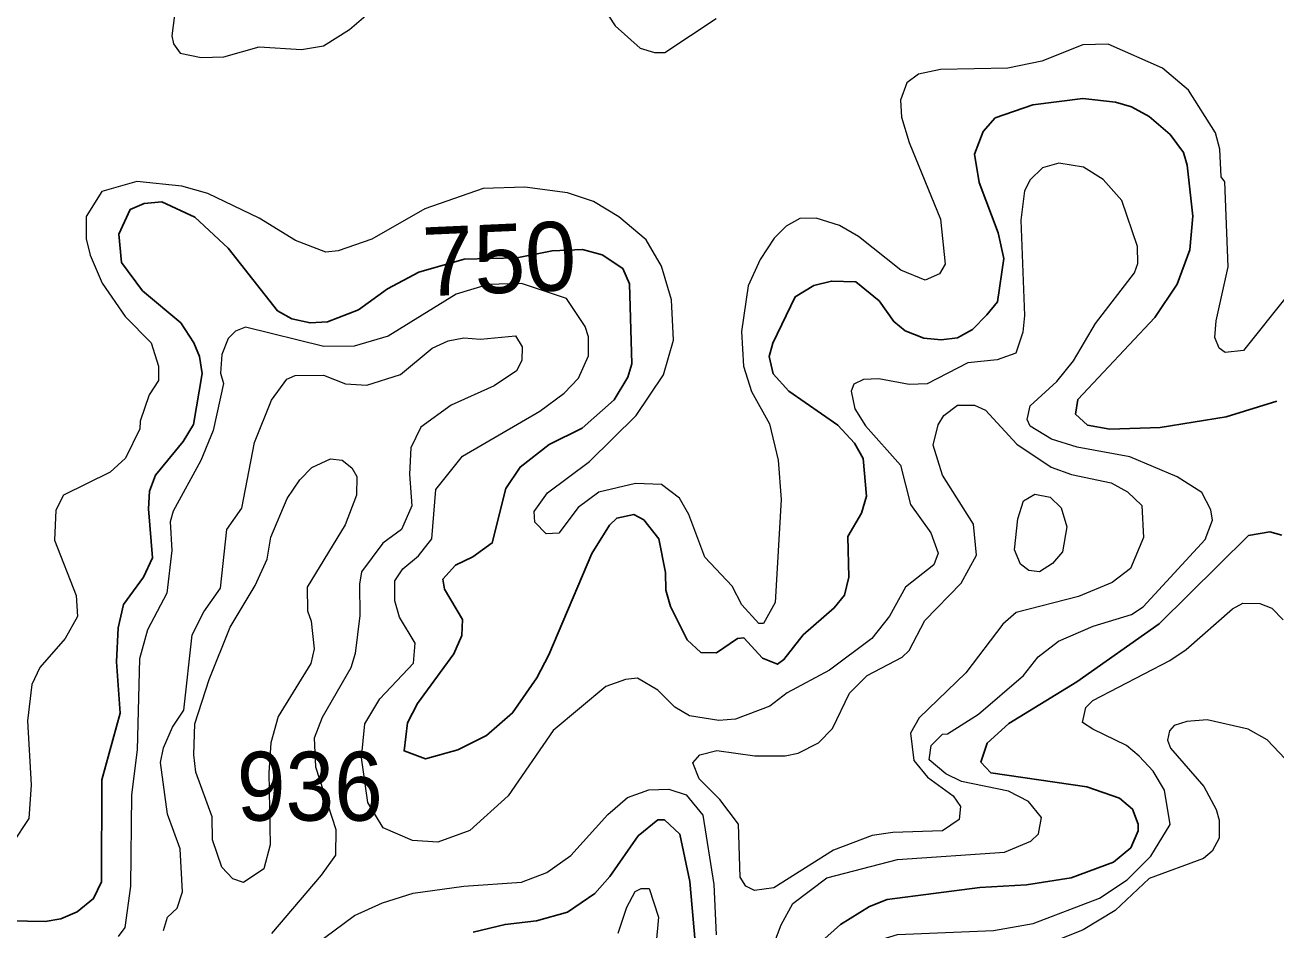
# Model space of a CAD drawing. Extents: x 763.2 to 816.8, y 7896.5 to 7952.7.
# Drawn here: x 774.565 to 777.47, y 7924.125 to 7926.226 of the extents above; entities that cross this region are included whole.
import ezdxf
from ezdxf.enums import TextEntityAlignment as Align

# ---------------------------------------------------------------- set-up
doc = ezdxf.new("R2010")
doc.units = 0
doc.header["$LTSCALE"] = 0.064
doc.layers.add('1', color=7, linetype='Continuous', lineweight=25)
doc.layers.add('2', color=7, linetype='Continuous', lineweight=13)
doc.layers.add('21', color=7, linetype='Continuous')
doc.layers.add('61', color=7, linetype='Continuous')

msp = doc.modelspace()

# ---------------------------------------------------------------- linework, layer by layer
at = {"layer": '1'}
for points in [[(776.1029, 7924.7983), (776.1344, 7924.7692), (776.1706, 7924.7687), (776.2194, 7924.8015), (776.2341, 7924.8031), (776.2781, 7924.7558), (776.3122, 7924.7417), (776.3275, 7924.7526), (776.3725, 7924.8102), (776.4445, 7924.8728), (776.4685, 7924.902), (776.4783, 7924.9438), (776.4756, 7925.0388), (776.508, 7925.0925), (776.5196, 7925.1319), (776.5113, 7925.22), (776.4913, 7925.2556), (776.4527, 7925.2973), (776.339, 7925.3761), (776.3024, 7925.4164), (776.2933, 7925.4565), (776.3016, 7925.4874), (776.3539, 7925.5951), (776.3966, 7925.6215), (776.4377, 7925.6315), (776.4943, 7925.6295), (776.5485, 7925.5859), (776.5827, 7925.5376), (776.6092, 7925.5162), (776.6521, 7925.4988), (776.693, 7925.4953), (776.7309, 7925.5), (776.7658, 7925.5195), (776.799, 7925.5529), (776.8236, 7925.5831), (776.8384, 7925.6843), (776.825, 7925.744), (776.7812, 7925.8609), (776.7702, 7925.9262), (776.7906, 7925.9792), (776.8184, 7926.0104), (776.9058, 7926.0413), (777.0217, 7926.0553), (777.0973, 7926.0471), (777.1351, 7926.0359), (777.176, 7926.0139), (777.2243, 7925.9721), (777.2556, 7925.9306), (777.2641, 7925.901), (777.2772, 7925.782), (777.2706, 7925.7039), (777.2407, 7925.6243), (777.189, 7925.5467), (777.0103, 7925.3565), (777.0049, 7925.3226), (777.0324, 7925.2972), (777.0842, 7925.2881), (777.2015, 7925.2917), (777.3547, 7925.3163), (777.4722, 7925.3529)], [(774.5295, 7924.1458), (774.6115, 7924.1447), (774.6478, 7924.1509), (774.6859, 7924.1667), (774.7241, 7924.1977), (774.7427, 7924.2362), (774.7432, 7924.4738), (774.7857, 7924.6283), (774.7777, 7924.7473), (774.781, 7924.8262), (774.7939, 7924.8807), (774.8397, 7924.9439), (774.8612, 7924.9891), (774.8516, 7925.1024), (774.8539, 7925.1434), (774.8682, 7925.1812), (774.9325, 7925.2591), (774.9563, 7925.2989), (774.9763, 7925.4171), (774.97, 7925.4566), (774.9569, 7925.4885), (774.9266, 7925.5347), (774.838, 7925.6091), (774.7891, 7925.675), (774.7829, 7925.7406), (774.8089, 7925.7982), (774.8418, 7925.8121), (774.8825, 7925.8154), (774.9593, 7925.7797), (775.0368, 7925.7077), (775.1509, 7925.5627), (775.1843, 7925.5443), (775.2271, 7925.5346), (775.2674, 7925.5367), (775.3397, 7925.565), (775.407, 7925.6134), (775.4792, 7925.6523), (775.5846, 7925.6829), (775.7072, 7925.6856), (775.7889, 7925.702), (775.8597, 7925.7047), (775.9053, 7925.6929), (775.9533, 7925.661), (775.969, 7925.6249), (775.974, 7925.4392), (775.965, 7925.4084), (775.9333, 7925.3561), (775.859, 7925.2898), (775.7819, 7925.2518), (775.7151, 7925.1997), (775.6818, 7925.1497), (775.6499, 7925.0236), (775.6049, 7924.991), (775.5649, 7924.9722), (775.5355, 7924.9396), (775.5389, 7924.916), (775.5809, 7924.8459), (775.5796, 7924.8083), (775.5611, 7924.7664), (775.4761, 7924.6503), (775.4532, 7924.606), (775.4453, 7924.5406), (775.495, 7924.5225), (775.5698, 7924.543), (775.6364, 7924.5762), (775.6974, 7924.6288), (775.7534, 7924.7105), (775.7817, 7924.7637), (775.8813, 7924.9987), (775.9221, 7925.0646), (775.9394, 7925.0814), (775.9792, 7925.0899), (776.002, 7925.0774)], [(776.002, 7925.0774), (776.0371, 7925.0332), (776.0527, 7924.9552), (776.0532, 7924.9142), (776.0642, 7924.8763), (776.1029, 7924.7983)], [(777.4837, 7925.0417), (777.4564, 7925.0495), (777.4066, 7925.041), (777.1994, 7924.8356), (777.0078, 7924.7013), (776.8501, 7924.6043), (776.7992, 7924.5582), (776.7852, 7924.5143), (776.8082, 7924.4893), (777.0311, 7924.457), (777.107, 7924.4312), (777.1374, 7924.4053), (777.1504, 7924.3701), (777.1501, 7924.3547), (777.1333, 7924.3158), (777.0931, 7924.2823), (776.9946, 7924.2462), (776.8911, 7924.2298), (776.7827, 7924.2232), (776.5671, 7924.1957), (776.5263, 7924.1795), (776.4588, 7924.1376), (776.408, 7924.0916)], [(776.1235, 7924.071), (776.1089, 7924.2371), (776.0856, 7924.3473), (776.05, 7924.3803), (776.0349, 7924.3806), (775.9887, 7924.343), (775.9231, 7924.2488), (775.8882, 7924.2096), (775.8252, 7924.1659), (775.753, 7924.146), (775.6799, 7924.1376), (775.606, 7924.1193)]]:
    msp.add_lwpolyline(points, dxfattribs=at)
at = {"layer": '2'}
for points in [[(775.8797, 7926.31), (775.9355, 7926.2244), (775.9938, 7926.1723), (776.027, 7926.1626), (776.0512, 7926.1626), (776.1698, 7926.2417)], [(774.9124, 7926.2489), (774.9058, 7926.2008), (774.9099, 7926.1825), (774.9252, 7926.1606), (774.9739, 7926.1509), (775.0265, 7926.1527), (775.1087, 7926.1754), (775.2073, 7926.1691), (775.258, 7926.1781), (775.3186, 7926.216), (775.378, 7926.2667)], [(777.0803, 7926.1819), (777.0217, 7926.1805), (776.9266, 7926.1422), (776.8476, 7926.1262), (776.6908, 7926.1226), (776.6397, 7926.1119)], [(777.4966, 7925.5974), (777.3952, 7925.4705), (777.3527, 7925.466), (777.3381, 7925.476), (777.3284, 7925.5007), (777.3316, 7925.5394), (777.3595, 7925.6646), (777.3512, 7925.8621), (777.343, 7925.8739), (777.3396, 7925.9379), (777.3301, 7925.9759), (777.2674, 7926.0752), (777.2066, 7926.126), (777.0803, 7926.1819)], [(776.6397, 7926.1119), (776.6127, 7926.0918), (776.5986, 7926.0518), (776.6005, 7926.0122), (776.6183, 7925.9536), (776.6908, 7925.7755), (776.7018, 7925.6711), (776.6891, 7925.6486), (776.6555, 7925.6334), (776.5991, 7925.6566), (776.501, 7925.7354), (776.4567, 7925.7606), (776.4024, 7925.7777), (776.3642, 7925.7773), (776.3326, 7925.7593), (776.3047, 7925.7313), (776.2725, 7925.6821), (776.2448, 7925.6203), (776.2288, 7925.5143), (776.2338, 7925.4343), (776.2519, 7925.3752), (776.2941, 7925.3002), (776.3144, 7925.216), (776.3209, 7925.1245), (776.3074, 7924.8856), (776.2799, 7924.8366), (776.2695, 7924.8361), (776.2295, 7924.8801), (776.2076, 7924.9228), (776.1435, 7924.9906), (776.1068, 7925.0897), (776.085, 7925.1274), (776.0429, 7925.1589), (775.983, 7925.1615), (775.8978, 7925.1418), (775.8499, 7925.1061), (775.8049, 7925.0463), (775.7755, 7925.045), (775.749, 7925.0719), (775.7475, 7925.0967), (775.7785, 7925.1401), (775.8756, 7925.2123), (775.9844, 7925.3198), (776.0476, 7925.414), (776.071, 7925.4941), (776.0661, 7925.588), (776.0435, 7925.6663), (776.0079, 7925.7273), (775.9444, 7925.781), (775.8851, 7925.8165), (775.8245, 7925.8368), (775.7259, 7925.85), (775.6288, 7925.8467), (775.4938, 7925.7997), (775.3701, 7925.7287), (775.292, 7925.7022), (775.2636, 7925.6989), (775.1928, 7925.7255), (775.109, 7925.778), (774.9896, 7925.8351), (774.9291, 7925.852), (774.8247, 7925.8632), (774.743, 7925.8396), (774.7071, 7925.7819), (774.707, 7925.7301), (774.7164, 7925.692), (774.7442, 7925.6271), (774.7977, 7925.5496), (774.8576, 7925.4885), (774.8745, 7925.4343), (774.8746, 7925.4011), (774.8533, 7925.3678), (774.8322, 7925.3067), (774.8313, 7925.2883), (774.7984, 7925.2205), (774.7623, 7925.1875), (774.6539, 7925.1343), (774.6366, 7925.0997), (774.6333, 7925.0302), (774.684, 7924.9012), (774.687, 7924.8525), (774.6584, 7924.802), (774.5993, 7924.7344), (774.5805, 7924.6947), (774.5706, 7924.6108), (774.5788, 7924.4621), (774.5739, 7924.3833), (774.5356, 7924.3265)], [(777.1126, 7925.8185), (777.069, 7925.8676), (777.0236, 7925.8963), (776.9658, 7925.9058), (776.9281, 7925.8945), (776.8995, 7925.8665), (776.8862, 7925.8411), (776.878, 7925.7728), (776.8861, 7925.5519), (776.8827, 7925.5132), (776.8665, 7925.4645), (776.8227, 7925.4491), (776.7543, 7925.4421), (776.6601, 7925.3928), (776.6182, 7925.3914), (776.5476, 7925.4047), (776.5124, 7925.4028), (776.4901, 7925.3923), (776.4837, 7925.3759), (776.492, 7925.3348), (776.5173, 7925.2954), (776.5982, 7925.2038), (776.6217, 7925.1127), (776.6688, 7925.0471), (776.6856, 7925), (776.6758, 7924.973), (776.6102, 7924.9211), (776.5726, 7924.8531), (776.5313, 7924.802), (776.4332, 7924.7281), (776.3353, 7924.6758), (776.2951, 7924.6442), (776.215, 7924.6141), (776.1762, 7924.611), (776.1083, 7924.6222), (776.0745, 7924.6425), (776.0347, 7924.6817), (775.9872, 7924.7093), (775.9593, 7924.7062), (775.9139, 7924.6901), (775.7917, 7924.5878), (775.6873, 7924.4364), (775.5977, 7924.3561), (775.5235, 7924.3286), (775.4652, 7924.3325), (775.397, 7924.3618), (775.3608, 7924.4206), (775.3463, 7924.5245), (775.3544, 7924.6031), (775.3891, 7924.6618), (775.4669, 7924.7444), (775.4707, 7924.7904), (775.4344, 7924.8515), (775.4236, 7924.8893), (775.4237, 7924.9357), (775.4426, 7924.9636), (775.4788, 7924.9933), (775.5096, 7925.033), (775.519, 7925.1476), (775.5808, 7925.2248), (775.7608, 7925.3299), (775.8174, 7925.3714), (775.8502, 7925.4058), (775.8738, 7925.4581), (775.8739, 7925.5018), (775.8655, 7925.5263), (775.8227, 7925.591), (775.718, 7925.6257), (775.6406, 7925.624), (775.5666, 7925.6014), (775.4085, 7925.504), (775.3296, 7925.4807), (775.2586, 7925.4794), (775.0766, 7925.5244), (775.0534, 7925.5151), (775.0366, 7925.4986), (775.0223, 7925.4615), (775.0192, 7925.4176), (775.0257, 7925.3936), (775.0015, 7925.2845), (774.9735, 7925.2147), (774.9087, 7925.0976), (774.9022, 7925.0722), (774.9057, 7925.0063), (774.8946, 7924.9069), (774.8494, 7924.8215), (774.8304, 7924.7546), (774.8252, 7924.5428), (774.8122, 7924.4383), (774.8101, 7924.2266), (774.7963, 7924.1302), (774.7811, 7924.1093)], [(776.2934, 7924.0629), (776.3211, 7924.1365), (776.3481, 7924.1864), (776.4271, 7924.2456), (776.5915, 7924.2884), (776.8401, 7924.3053), (776.9007, 7924.3306), (776.9185, 7924.3478), (776.9254, 7924.3858), (776.8959, 7924.4234), (776.8493, 7924.4473), (776.7396, 7924.4693), (776.7035, 7924.4872), (776.6649, 7924.5202), (776.6694, 7924.5533), (776.6957, 7924.5792), (776.7072, 7924.5804), (776.7793, 7924.6258), (776.8841, 7924.7157), (776.9181, 7924.7593), (776.9656, 7924.7953), (777.0459, 7924.8306), (777.1346, 7924.857), (777.1618, 7924.8753), (777.3058, 7925.0314), (777.3231, 7925.0761), (777.3194, 7925.1006), (777.2982, 7925.1404), (777.241, 7925.1771), (777.1308, 7925.2234), (777.0088, 7925.2458), (776.9493, 7925.2648), (776.8995, 7925.295), (776.8927, 7925.31), (776.8992, 7925.3416), (776.9616, 7925.3982), (777.0001, 7925.4461), (777.051, 7925.5335), (777.142, 7925.6507), (777.1492, 7925.6724), (777.1489, 7925.7118), (777.1126, 7925.8185)], [(774.8866, 7924.1233), (774.8958, 7924.1547), (774.9184, 7924.1753), (774.9309, 7924.2131), (774.9251, 7924.3129), (774.8958, 7924.3935), (774.8796, 7924.5138), (774.8865, 7924.5474), (774.9072, 7924.5955), (774.9337, 7924.6352), (774.9529, 7924.8099), (774.9801, 7924.8635), (775.019, 7924.9184), (775.0338, 7925.055), (775.0684, 7925.1042), (775.0982, 7925.2568), (775.1373, 7925.3548), (775.1727, 7925.4036), (775.1923, 7925.4126), (775.2579, 7925.4131), (775.3092, 7925.393), (775.3585, 7925.3901), (775.4366, 7925.4146), (775.5102, 7925.4761), (775.5474, 7925.4926), (775.5839, 7925.5), (775.6231, 7925.4969), (775.7038, 7925.5047), (775.7193, 7925.4789), (775.719, 7925.4471), (775.7062, 7925.4234), (775.6542, 7925.3886), (775.5545, 7925.3435), (775.4843, 7925.2925), (775.4613, 7925.2446), (775.458, 7925.1829), (775.4629, 7925.1096), (775.4396, 7925.055), (775.3957, 7925.0231), (775.3465, 7924.9564), (775.3414, 7924.9281), (775.3428, 7924.8552), (775.3314, 7924.767), (775.3213, 7924.7336), (775.2553, 7924.6178), (775.2364, 7924.5705), (775.2396, 7924.5035), (775.2867, 7924.3584), (775.2857, 7924.2988), (775.253, 7924.2517), (775.1376, 7924.1162)], [(776.5048, 7924.0877), (776.5911, 7924.1143), (776.8141, 7924.1233), (776.9066, 7924.1395), (777.0602, 7924.1986), (777.1244, 7924.2412), (777.1793, 7924.2959), (777.2245, 7924.3694), (777.2116, 7924.4491), (777.1852, 7924.4936), (777.1524, 7924.5287), (777.123, 7924.5531), (777.0449, 7924.5908), (777.0211, 7924.6068), (777.029, 7924.6414), (777.0453, 7924.6576), (777.2241, 7924.7503), (777.2614, 7924.7757), (777.3694, 7924.8705), (777.3931, 7924.8838), (777.4326, 7924.8826), (777.4607, 7924.8722), (777.4872, 7924.8446)], [(777.5607, 7924.4496), (777.4498, 7924.5665), (777.4055, 7924.5911), (777.3102, 7924.6124), (777.2635, 7924.609), (777.234, 7924.5998), (777.223, 7924.5872), (777.2186, 7924.5658), (777.2252, 7924.5466), (777.3027, 7924.4577), (777.3317, 7924.4049), (777.3383, 7924.38), (777.3382, 7924.338), (777.3219, 7924.3075), (777.3018, 7924.2907), (777.1755, 7924.2443), (777.0969, 7924.1696), (777.0223, 7924.1251), (776.9551, 7924.0983)], [(775.2372, 7924.0894), (775.3303, 7924.1581), (775.3951, 7924.1877), (775.4663, 7924.2099), (775.584, 7924.2262), (775.7176, 7924.2354), (775.777, 7924.2586), (775.8322, 7924.2979), (775.9188, 7924.3928), (775.9639, 7924.4322), (776.014, 7924.4503), (776.0598, 7924.4517), (776.1001, 7924.4385), (776.1395, 7924.391), (776.1649, 7924.23), (776.1705, 7924.1131)], [(775.9428, 7924.117), (775.9624, 7924.1781), (775.9821, 7924.2141), (775.9961, 7924.2214), (776.0145, 7924.2214), (776.0365, 7924.1544), (776.03, 7924.0873)]]:
    msp.add_lwpolyline(points, dxfattribs=at)
for points in [[(776.7745, 7924.9951), (776.7675, 7925.0668), (776.6956, 7925.1813), (776.6742, 7925.2508), (776.6859, 7925.298), (776.699, 7925.3191), (776.7308, 7925.3438), (776.7703, 7925.3438), (776.7958, 7925.3322), (776.8686, 7925.2532), (776.948, 7925.1996), (776.9953, 7925.1827), (777.0874, 7925.1628), (777.1252, 7925.1422), (777.1587, 7925.1103), (777.1623, 7925.0363), (777.1323, 7924.9645), (777.0899, 7924.9314), (777.0118, 7924.8988), (776.8666, 7924.8622), (776.8359, 7924.8348), (776.7502, 7924.7216), (776.6415, 7924.6174), (776.6216, 7924.5815), (776.6296, 7924.5183), (776.661, 7924.4797), (776.7205, 7924.4361), (776.7379, 7924.4115), (776.7347, 7924.3811), (776.6956, 7924.3548), (776.5805, 7924.3512), (776.5321, 7924.3438), (776.4427, 7924.3101), (776.3038, 7924.2229), (776.2593, 7924.2165), (776.2388, 7924.2266), (776.2256, 7924.2476), (776.2221, 7924.3703), (776.1783, 7924.428), (776.1303, 7924.4756), (776.1163, 7924.5132), (776.132, 7924.5318), (776.1715, 7924.5416), (776.2602, 7924.5289), (776.33, 7924.5288), (776.3609, 7924.5357), (776.4075, 7924.5592), (776.4404, 7924.5927), (776.4801, 7924.675), (776.5207, 7924.7155), (776.6023, 7924.758), (776.6181, 7924.7734), (776.6549, 7924.8432), (776.7392, 7924.9304)], [(774.9568, 7924.5312), (774.9592, 7924.6032), (774.9925, 7924.7066), (775.0412, 7924.8276), (775.0997, 7924.9249), (775.1269, 7924.9859), (775.1355, 7925.037), (775.174, 7925.1269), (775.2029, 7925.1702), (775.231, 7925.1988), (775.2742, 7925.2186), (775.3012, 7925.2156), (775.3242, 7925.1979), (775.3355, 7925.1781), (775.3345, 7925.1346), (775.3081, 7925.0655), (775.2199, 7924.9208), (775.221, 7924.8658), (775.2296, 7924.8419), (775.2361, 7924.7774), (775.229, 7924.7439), (775.153, 7924.6205), (775.1358, 7924.5594), (775.1309, 7924.4899), (775.1342, 7924.3226), (775.1199, 7924.2669), (775.0726, 7924.235), (775.0472, 7924.2432), (775.0219, 7924.2705), (775.0001, 7924.3339), (774.9998, 7924.3873), (774.9617, 7924.4916)], [(776.8634, 7925.0077), (776.8705, 7925.0798), (776.8843, 7925.1211), (776.91, 7925.1367), (776.9462, 7925.1295), (776.9716, 7925.1051), (776.9843, 7925.0611), (776.9749, 7925.0027), (776.9516, 7924.9758), (776.9209, 7924.9562), (776.8962, 7924.9596), (776.8769, 7924.974)]]:
    msp.add_lwpolyline(points, close=True, dxfattribs=at)

# ---------------------------------------------------------------- texts
at = {"layer": '21', "width": 0.95}
msp.add_text('936', height=0.16, dxfattribs=at).set_placement((775.0567, 7924.3786))
at = {"layer": '61'}
msp.add_text('750', height=0.16, rotation=2.536, dxfattribs=at).set_placement((775.67, 7925.6039), align=Align.CENTER)

doc.saveas('drawing.dxf')
